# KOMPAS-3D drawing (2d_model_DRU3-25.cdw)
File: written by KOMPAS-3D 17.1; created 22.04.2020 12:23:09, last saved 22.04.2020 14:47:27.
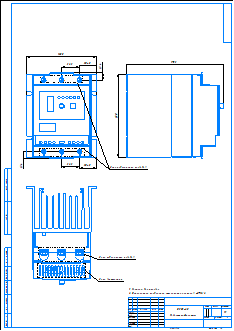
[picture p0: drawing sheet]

Sheet 1: A2, portrait

Title block, sheet 1: name: DRU3-25 / Габаритный чертеж; sheets: 1; sheet format: A2; stored path: E:\Марк\DRU3\DRU3-XX\2d_model_DRU3-25.cdw

Referenced files in C:\Temp\Rar$DIa0.533\: HHT25ЙўИИЖч_40A.m3d, 100AµзБ¦µчХыЖчµЧЧщ.m3d, 100AµзБ¦µчХыЖчЙПёЗ(2014.5.12РЮёД).m3d, 100AµзБ¦µчХыЖчЅУПЯЧщ.m3d, 100AµзБ¦µчХыЖчЅУПЯЖ¬.m3d, µзБ¦µчХыЖчРэЕҐ.m3d, M6.m3d, 25A¦ч+ж¦ў-v¦ў.a3d
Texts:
  Пользователь Windows
  HHT25ЙўИИЖч_40A
  100AµзБ¦µчХыЖчЙПёЗ(2014.5.12РЮёД)
  µзБ¦µчХыЖчРэЕҐ
Dimensions and other numbers on the sheet: 1:1; 1; 100AµзБ¦µчХыЖчµЧЧщ; 100AµзБ¦µчХыЖчЅУПЯЧщ; 100AµзБ¦µчХыЖчЅУПЯЖ¬; 25AµзБ¦µчХыЖч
